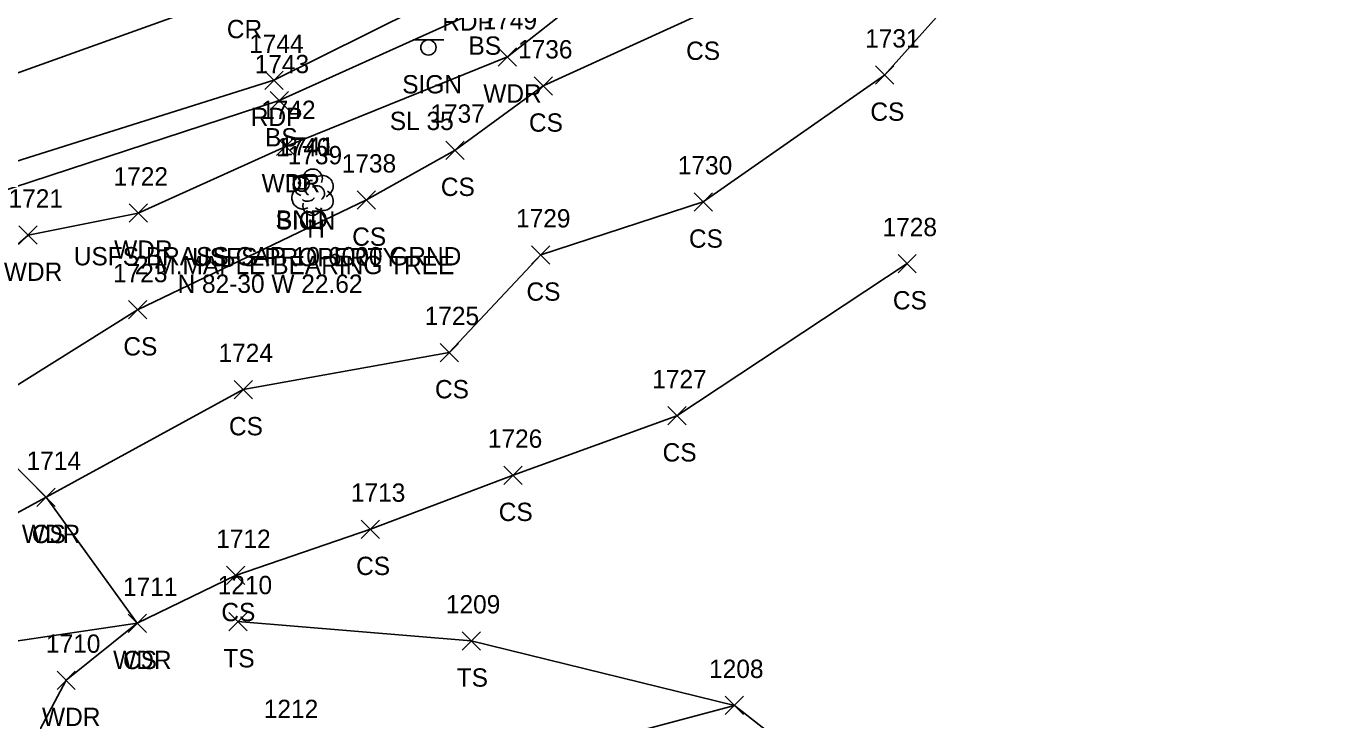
# Model space of a CAD drawing. Extents: x 1499292 to 1501024, y 534584 to 538043.
# Drawn here: x 1500027.5 to 1500170.2, y 537564.4 to 537640.2 of the extents above; entities that cross this region are included whole.
import ezdxf

# ---------------------------------------------------------------- set-up
doc = ezdxf.new("R2010")
doc.units = 0
for name, color, linetype in [('L_A', 7, 'Continuous'), ('L_C', 7, 'Continuous'), ('L_I', 7, 'Continuous'), ('L_TIC', 7, 'Continuous'), ('LAWA', 7, 'Continuous'), ('LELB', 7, 'Continuous'), ('Level 18', 7, 'Continuous'), ('LTD', 7, 'Continuous'), ('M_A', 7, 'Continuous'), ('M_C', 7, 'Continuous'), ('M_I', 7, 'Continuous'), ('P_A', 7, 'Continuous'), ('P_I', 7, 'Continuous'), ('P_TIC', 7, 'Continuous'), ('PET', 7, 'Continuous'), ('PRC', 7, 'Continuous'), ('S_A', 7, 'Continuous'), ('S_C', 7, 'Continuous'), ('S_I', 7, 'Continuous'), ('SSGN', 7, 'Continuous')]:
    doc.layers.add(name, color=color, linetype=linetype)

msp = doc.modelspace()

# ---------------------------------------------------------------- linework, layer by layer
at = {"layer": 'L_TIC'}
for points in [[(1500079.12, 537635.85), (1500081.12, 537637.85)], [(1500081.12, 537635.85), (1500079.12, 537637.85)], [(1500120.36, 537633.87), (1500122.36, 537635.87)], [(1500122.36, 537633.87), (1500120.36, 537635.87)], [(1500083.04, 537632.68), (1500085.04, 537634.68)], [(1500085.04, 537632.68), (1500083.04, 537634.68)], [(1500054.19, 537631.07), (1500056.19, 537633.07)], [(1500056.19, 537631.07), (1500054.19, 537633.07)], [(1500054.9, 537626.07), (1500056.9, 537628.07)], [(1500056.9, 537626.07), (1500054.9, 537628.07)], [(1500073.41, 537625.66), (1500075.41, 537627.66)], [(1500075.41, 537625.66), (1500073.41, 537627.66)], [(1500063.72, 537620.22), (1500065.72, 537622.22)], [(1500065.72, 537620.22), (1500063.72, 537622.22)], [(1500063.72, 537620.22), (1500065.72, 537622.22)], [(1500065.72, 537620.22), (1500063.72, 537622.22)], [(1500100.53, 537620.01), (1500102.53, 537622.01)], [(1500102.53, 537620.01), (1500100.53, 537622.01)], [(1500038.78, 537618.8), (1500040.78, 537620.8)], [(1500040.78, 537618.8), (1500038.78, 537620.8)], [(1500026.73, 537616.39), (1500028.73, 537618.39)], [(1500028.73, 537616.39), (1500026.73, 537618.39)], [(1500082.77, 537614.22), (1500084.77, 537616.22)], [(1500084.77, 537614.22), (1500082.77, 537616.22)], [(1500122.82, 537613.27), (1500124.82, 537615.27)], [(1500124.82, 537613.27), (1500122.82, 537615.27)], [(1500038.71, 537608.24), (1500040.71, 537610.24)], [(1500040.71, 537608.24), (1500038.71, 537610.24)], [(1500072.77, 537603.56), (1500074.77, 537605.56)], [(1500074.77, 537603.56), (1500072.77, 537605.56)], [(1500050.25, 537599.52), (1500052.25, 537601.52)], [(1500052.25, 537599.52), (1500050.25, 537601.52)], [(1500097.65, 537596.66), (1500099.65, 537598.66)], [(1500099.65, 537596.66), (1500097.65, 537598.66)], [(1500079.74, 537590.16), (1500081.74, 537592.16)], [(1500081.74, 537590.16), (1500079.74, 537592.16)], [(1500028.7, 537587.75), (1500030.7, 537589.75)], [(1500030.7, 537587.75), (1500028.7, 537589.75)], [(1500028.7, 537587.75), (1500030.7, 537589.75)], [(1500030.7, 537587.75), (1500028.7, 537589.75)], [(1500064.15, 537584.26), (1500066.15, 537586.26)], [(1500066.15, 537584.26), (1500064.15, 537586.26)], [(1500049.42, 537579.22), (1500051.42, 537581.22)], [(1500051.42, 537579.22), (1500049.42, 537581.22)], [(1500038.67, 537573.99), (1500040.67, 537575.99)], [(1500040.67, 537573.99), (1500038.67, 537575.99)], [(1500038.67, 537573.99), (1500040.67, 537575.99)], [(1500040.67, 537573.99), (1500038.67, 537575.99)], [(1500049.67, 537574.17), (1500051.67, 537576.17)], [(1500051.67, 537574.17), (1500049.67, 537576.17)], [(1500075.18, 537572.07), (1500077.18, 537574.07)], [(1500077.18, 537572.07), (1500075.18, 537574.07)], [(1500030.9, 537567.77), (1500032.9, 537569.77)], [(1500032.9, 537567.77), (1500030.9, 537569.77)], [(1500103.94, 537565.02), (1500105.94, 537567.02)], [(1500105.94, 537565.02), (1500103.94, 537567.02)], [(1500103.94, 537565.02), (1500105.94, 537567.02)], [(1500105.94, 537565.02), (1500103.94, 537567.02)]]:
    msp.add_lwpolyline(points, dxfattribs=at)
at = {"layer": 'LAWA'}
msp.add_lwpolyline([(1500024.22, 537554.38), (1500031.9, 537568.77), (1500039.67, 537574.99), (1500029.7, 537588.75), (1500020.95, 537597.49), (1500010.79, 537602.57), (1500027.73, 537617.39), (1500039.78, 537619.8), (1500055.9, 537627.07), (1500080.12, 537636.85), (1500101.28, 537653.44), (1500116.59, 537661.83), (1500123.9, 537666.76), (1500144.25, 537687.7), (1500160.49, 537705.32)], dxfattribs=at)
at = {"layer": 'LELB'}
for points in [[(1499939.76, 537563.39), (1499940.61, 537580.36), (1499946.14, 537588.19), (1499959.54, 537588.6), (1499966.34, 537595.38), (1499978.12, 537601.79), (1500000.32, 537612.94), (1500023.87, 537621.84), (1500055.19, 537632.07), (1500077.43, 537642.08), (1500099.37, 537656.6), (1500118.26, 537674.35), (1500140.84, 537690.31), (1500154.39, 537710.04)], [(1499979.56, 537592.44), (1499996.38, 537588.9), (1500018.65, 537582.77), (1500029.7, 537588.75), (1500051.25, 537600.52), (1500073.77, 537604.56), (1500083.77, 537615.22), (1500101.53, 537621.01), (1500121.36, 537634.87), (1500131.46, 537646.17), (1500127.8, 537658.31), (1500115.88, 537649.33), (1500101.22, 537641.52), (1500084.04, 537633.68), (1500074.41, 537626.66), (1500064.72, 537621.22)], [(1500020.95, 537597.49), (1500039.71, 537609.24), (1500064.72, 537621.22)], [(1499969.38, 537571.36), (1499994.33, 537569.2), (1500017.52, 537571.72), (1500039.67, 537574.99), (1500050.42, 537580.22), (1500065.15, 537585.26), (1500080.74, 537591.16), (1500098.65, 537597.66), (1500123.82, 537614.27)], [(1500104.94, 537566.02), (1500076.18, 537573.07), (1500050.67, 537575.17)], [(1500071.44, 537533.34), (1500092.78, 537525.77), (1500113.32, 537512.39), (1500125.76, 537504.08), (1500142.13, 537491.72), (1500147.83, 537500.24), (1500145.6, 537512.61), (1500170.24, 537505.74), (1500161.32, 537537.08), (1500144.36, 537544.45), (1500125.84, 537549.67), (1500104.94, 537566.02), (1500074.25, 537557.81), (1500055.63, 537561.64), (1500041.07, 537552.42), (1500031.31, 537541.64)]]:
    msp.add_lwpolyline(points, dxfattribs=at)
at = {"layer": 'Level 18'}
msp.add_lwpolyline([(1500056.74, 537623.7), (1500057.99, 537623.7), (1500057.99, 537622.45), (1500056.74, 537622.45)], close=True, dxfattribs=at)
msp.add_circle((1500057.36, 537623.08), 0.0833, dxfattribs=at)
at = {"layer": 'LTD'}
msp.add_line((1500058.81, 537622.12), (1500058.81, 537622.12), dxfattribs=at)
msp.add_line((1500058.81, 537622.12), (1500058.81, 537622.12), dxfattribs=at)
msp.add_arc((1500058.85, 537623.55), 1.05, 335.5272, 180.9563, dxfattribs=at)
for centre, major_axis, ratio, start_param, end_param in [((1500058.01, 537622.78), (1.21, -0.51), 0.895232, 1.570796, 4.712389), ((1500059.85, 537622.7), (-1.14, -0.48), 0.949671, 1.570796, 4.712389), ((1500057.72, 537621.41), (0.58, -1.04), 0.959034, 3.141593, 6.283185), ((1500058.6, 537622.57), (-0.208, -0.792), 0.645439, 3.141593, 6.283185), ((1500059.31, 537621.95), (-0.5, 0.667), 0.989748, 3.141593, 6.283185), ((1500058.35, 537621.37), (-0.625, -0.083), 0.423636, 0, 3.141593), ((1500059.81, 537621.28), (-1.09, 0.79), 0.841452, 1.570796, 4.712389), ((1500058.81, 537620.62), (0.26, 1.06), 0.942809, 1.570796, 4.712389)]:
    msp.add_ellipse(centre, major_axis=major_axis, ratio=ratio, start_param=start_param, end_param=end_param, dxfattribs=at)
at = {"layer": 'P_TIC'}
for points in [[(1500053.6, 537633.29), (1500055.6, 537635.29)], [(1500055.6, 537633.29), (1500053.6, 537635.29)]]:
    msp.add_lwpolyline(points, dxfattribs=at)
at = {"layer": 'PET'}
msp.add_lwpolyline([(1499935.87, 537560.72), (1499938.24, 537581.19), (1499942.18, 537591.79), (1499947.52, 537597.24), (1499960.42, 537604.64), (1499979.46, 537611.66), (1499998.98, 537617.33), (1500023, 537624.38), (1500054.6, 537634.29), (1500075.51, 537644.72), (1500098.08, 537658.76), (1500117.21, 537676.4), (1500137.33, 537696.2), (1500150.78, 537713.38)], dxfattribs=at)
at = {"layer": 'PRC'}
msp.add_lwpolyline([(1499909.99, 537586.35), (1499926.3, 537596.08), (1499940.36, 537606.28), (1499956.99, 537614.66), (1499975.82, 537621.46), (1499996.95, 537627.68), (1500020.51, 537632.92), (1500051.03, 537643.89), (1500070.71, 537652.73), (1500093.19, 537667.35), (1500110.6, 537684.33), (1500128.97, 537704), (1500143.04, 537721.07)], dxfattribs=at)
at = {"layer": 'SSGN'}
for p, q in [((1500069.84, 537638.71), (1500073.18, 537638.71)), ((1500071.49, 537637.88), (1500071.49, 537637.88)), ((1500055.99, 537623.84), (1500059.33, 537623.84)), ((1500057.64, 537623.01), (1500057.64, 537623.01))]:
    msp.add_line(p, q, dxfattribs=at)
for centre in [(1500071.49, 537637.88), (1500057.64, 537623.01)]:
    msp.add_circle(centre, 0.833, dxfattribs=at)

# ---------------------------------------------------------------- texts
at = {"layer": 'L_A'}
for s, p in [('BS', (1500075.87, 537637.08)), ('CS', (1500099.66, 537636.52)), ('WDR', (1500077.49, 537631.85)), ('CS', (1500119.8, 537629.87)), ('CS', (1500082.48, 537628.68)), ('BS', (1500053.63, 537627.07)), ('WDR', (1500053.26, 537622.07)), ('CS', (1500072.85, 537621.66)), ('H', (1500058.24, 537617.12)), ('CS', (1500063.16, 537616.22)), ('CS', (1500063.16, 537616.22)), ('WDR', (1500037.14, 537614.8)), ('CS', (1500099.97, 537616.01)), ('WDR', (1500025.09, 537612.39)), ('CS', (1500082.21, 537610.22)), ('CS', (1500122.26, 537609.27)), ('CS', (1500038.15, 537604.24)), ('CS', (1500072.21, 537599.56)), ('CS', (1500049.69, 537595.52)), ('CS', (1500097.09, 537592.66)), ('CS', (1500079.18, 537586.16)), ('WDR', (1500027.06, 537583.75)), ('CS', (1500028.14, 537583.75)), ('CS', (1500063.59, 537580.26)), ('CS', (1500048.86, 537575.22)), ('WDR', (1500037.03, 537569.99)), ('CS', (1500038.11, 537569.99)), ('TS', (1500049.08, 537570.17)), ('TS', (1500074.59, 537568.07)), ('WDR', (1500029.26, 537563.77))]:
    msp.add_text(s, height=2, dxfattribs=at).set_placement(p)
at = {"layer": 'L_C'}
msp.add_text('2 M.MAPLE BEARING TREE', height=2, dxfattribs=at).set_placement((1500039.41, 537613.12))
at = {"layer": 'L_I'}
for s, p in [('1749', (1500077.42, 537639.85)), ('1731', (1500119.23, 537637.87)), ('1736', (1500081.29, 537636.68)), ('1743', (1500052.5, 537635.07)), ('1742', (1500053.21, 537630.07)), ('1737', (1500071.71, 537629.66)), ('1739', (1500056.11, 537625.12)), ('1738', (1500062.02, 537624.22)), ('1738', (1500062.02, 537624.22)), ('1730', (1500098.75, 537624.01)), ('1722', (1500037.08, 537622.8)), ('1721', (1500025.6, 537620.39)), ('1729', (1500081.07, 537618.22)), ('1728', (1500121.13, 537617.27)), ('1723', (1500037.02, 537612.24)), ('1725', (1500071.08, 537607.56)), ('1724', (1500048.55, 537603.52)), ('1727', (1500095.96, 537600.66)), ('1726', (1500077.99, 537594.16)), ('1714', (1500027.57, 537591.75)), ('1714', (1500027.57, 537591.75)), ('1713', (1500063.02, 537588.26)), ('1712', (1500048.3, 537583.22)), ('1711', (1500038.11, 537577.99)), ('1711', (1500038.11, 537577.99)), ('1210', (1500048.46, 537578.17)), ('1209', (1500073.4, 537576.07)), ('1710', (1500029.69, 537571.77)), ('1208', (1500102.17, 537569.02)), ('1208', (1500102.17, 537569.02)), ('1212', (1500053.5, 537564.64))]:
    msp.add_text(s, height=2, dxfattribs=at).set_placement(p)
at = {"layer": 'M_A'}
msp.add_text('BND', height=2, dxfattribs=at).set_placement((1500054.85, 537618.08))
at = {"layer": 'M_C'}
for s, p in [('USFS BRASS CAP 10-6000 GRND', (1500032.73, 537614.08)), ('N 82-30 W 22.62', (1500044.07, 537611.08))]:
    msp.add_text(s, height=2, dxfattribs=at).set_placement(p)
at = {"layer": 'M_I'}
msp.add_text('1741', height=2, dxfattribs=at).set_placement((1500055.24, 537626.08))
at = {"layer": 'P_A'}
for s, p in [('RDP', (1500073, 537639.72)), ('CR', (1500049.46, 537638.89)), ('RDP', (1500052.08, 537629.29))]:
    msp.add_text(s, height=2, dxfattribs=at).set_placement(p)
at = {"layer": 'P_I'}
msp.add_text('1744', height=2, dxfattribs=at).set_placement((1500051.9, 537637.29))
at = {"layer": 'S_A'}
for p in [(1500068.63, 537632.86), (1500054.78, 537617.99)]:
    msp.add_text('SIGN', height=2, dxfattribs=at).set_placement(p)
at = {"layer": 'S_C'}
for s, p in [('SL 35', (1500067.27, 537628.86)), ('USFS PROPERTY', (1500045.67, 537613.99))]:
    msp.add_text(s, height=2, dxfattribs=at).set_placement(p)
at = {"layer": 'S_I'}
msp.add_text('1740', height=2, dxfattribs=at).set_placement((1500054.84, 537625.99))

doc.saveas('drawing.dxf')
